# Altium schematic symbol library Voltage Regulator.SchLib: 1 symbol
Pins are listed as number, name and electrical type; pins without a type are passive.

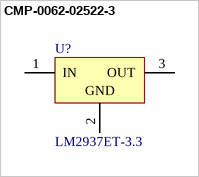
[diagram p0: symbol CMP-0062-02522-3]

## CMP-0062-02522-3
designator U?, comment LM2937ET-3.3
500 mA Low Dropout Regulator, 3-pin TO-220; Manufacturer: Texas Instruments; PackageTopMarking: NSUZXYTTE#*LM2937ET*-3.3; PowerWise: N; CompType: LDO IC
footprint NDE0003A (FM, 3-Leads, Body 10.7x4.7mm, Pitch 2.54mm)
pins: 1 IN (power), 2 GND (power), 3 OUT (power)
